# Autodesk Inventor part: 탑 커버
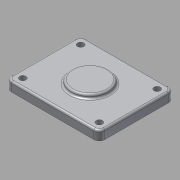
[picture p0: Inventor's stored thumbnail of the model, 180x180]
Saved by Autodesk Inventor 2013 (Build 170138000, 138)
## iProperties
Created: 2017-05
Part Number: 탑 커버
Material: 알루미늄 6061
Document SubType Name: Modeling
Designer: mduedu
Density: 1 g/cm^3
Author: mduedu
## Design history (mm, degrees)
sketch "스케치1"
  geometry: L1 (25, 20)-(-25, 20); L2 (-25, 20)-(-25, -20); L3 (-25, -20)-(25, -20); L4 (25, -20)-(25, 20); L5 (25, 20)-(-25, -20); L6 (-25, 20)-(25, -20); 1 further point
  constraints: 12 end point, 2 midpoint, 2 parallel, 1 horizontal, 1 perpendicular
  dimensions: "d0" = 50 distance of L3.end L2.end; "d1" = 40 distance of L2.end L1.end
extrude "돌출1" new body sketch "스케치1" distance "d2" = 5; taper "d3" = 0 deg
fillet "모깎기1" dims "d4" = 3
sketch "스케치2"
  geometry: C1 r 10 at (0, 0); 1 further point
  constraints: 1 centre point, 1 coincident
  dimensions: "d5" = 20 diameter of C1
extrude "돌출2" join sketch "스케치2" distance "d6" = 2; taper "d7" = 0 deg
sketch "스케치3"
  geometry: L1 (-16, -11)-(16, -11); L2 (16, -11)-(16, 11); L3 (16, 11)-(-16, 11); L4 (-16, 11)-(-16, -11); L5 (-16, -11)-(16, 11); L6 (16, -11)-(-16, 11); 1 further point
  constraints: 12 end point, 2 midpoint, 2 parallel, 1 horizontal, 1 perpendicular
  dimensions: "d8" = 32 distance of L3.end L2.end; "d9" = 22 distance of L2.end L1.end
extrude "돌출3" join sketch "스케치3" distance "d10" = 3; taper "d11" = 0 deg
fillet "모깎기2" dims "d12" = 3
sketch "스케치4"
  geometry: L1 (-13, -11)-(13, -11) reference; L2 (16, -8)-(16, 8) reference; L3 (13, 11)-(-13, 11) reference; L4 (-16, 8)-(-16, -8) reference; L5 (-13, 9)-(13, 9); L6 (14, 8)-(14, -8); L7 (13, -9)-(-13, -9); L8 (-14, -8)-(-14, 8); A1 r 3 centre (-13, -8) between (-16, -8) and (-13, -11) reference; A2 r 3 centre (13, -8) between (13, -11) and (16, -8) reference; A3 r 3 centre (13, 8) between (16, 8) and (13, 11) reference; A4 r 3 centre (-13, 8) between (-13, 11) and (-16, 8) reference; A5 r 1 centre (13, 8) between (14, 8) and (13, 9); A6 r 1 centre (13, -8) between (13, -9) and (14, -8); A7 r 1 centre (-13, -8) between (-14, -8) and (-13, -9); A8 r 1 centre (-13, 8) between (-13, 9) and (-14, 8); 1 further point
  constraints: 8 end point, 8 point on circle, 4 centre point, 7 other
  dimensions: "d13" = 2 distance between parallel lines of L5 L3
extrude "돌출4" cut sketch "스케치4" stored distance "d14" = 2; taper "d15" = 0 deg
chamfer "모따기1" distance "d16" = 1; stored, may be unused: second distance "d17" = 2, angle "d18" = 45 deg
fillet "모깎기3" dims "d19" = 1
fillet "모깎기4" dims "d20" = 1
fillet "모깎기5" dims "d21" = 1
sketch "스케치5"
  geometry: L1 (-20.5, -15.5)-(20.5, -15.5); L2 (20.5, -15.5)-(20.5, 15.5); L3 (20.5, 15.5)-(-20.5, 15.5); L4 (-20.5, 15.5)-(-20.5, -15.5); L5 (-20.5, -15.5)-(20.5, 15.5); L6 (20.5, -15.5)-(-20.5, 15.5); L7 (22, 20)-(-22, 20) reference; L8 (25, -17)-(25, 17) reference; 5 further points
  constraints: 12 end point, 4 coincident, 2 midpoint, 2 parallel, 1 horizontal, 1 perpendicular
  dimensions: "d22" = 4.5 distance between parallel lines of L3 L7; "d23" = 4.5 distance between parallel lines of L2 L8
sketch "스케치6"
  geometry: 4 further points
  constraints: 4 other
hole "구멍1" sketch "스케치6" at (-20.5, 15.5), (20.5, 15.5), (20.5, -15.5), (-20.5, -15.5) diameter "d24" = 3.4; stored, may be unused: countersink angle "d28" = 90 deg, drill point angle "d30" = 0 deg; dims "d25" = 6, "d26" = 4, "d27" = 2, "d29" = 8
node "솔리드1"
node "투영된 루프1"
